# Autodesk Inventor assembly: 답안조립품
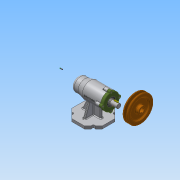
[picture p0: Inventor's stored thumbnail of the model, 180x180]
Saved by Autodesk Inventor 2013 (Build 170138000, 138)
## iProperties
Created: 2019-12
Part Number: 답안조립품
Document SubType Name: Assembly
Designer: Administrator
Author: Administrator
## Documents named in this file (12)
- C:\Users\Administrator\Desktop\491204V1062\답안조립품.iam
- C:\Users\Administrator\Desktop\491204V1062\본체.ipt
- C:\Users\Administrator\Desktop\491204V1062\V벨트풀리.ipt
- C:\Users\Administrator\Desktop\491204V1062\멈춤나사 M3.ipt
- C:\Users\Administrator\Desktop\491204V1062\베어링 6004.ipt
- C:\Users\Administrator\Desktop\491204V1062\베어링 51202.ipt
- C:\Users\Administrator\Desktop\491204V1062\볼트 M4.ipt
- C:\Users\Administrator\Desktop\491204V1062\어댑터슬리브.ipt
- C:\Users\Administrator\Desktop\491204V1062\오일 실.ipt
- C:\Users\Administrator\Desktop\491204V1062\축.ipt
- C:\Users\Administrator\Desktop\491204V1062\커버.ipt
- C:\Users\Administrator\Desktop\491204V1062\키 5 x 5 x 16.ipt
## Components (1 placed, 1 different names)
1. V벨트풀리:1
